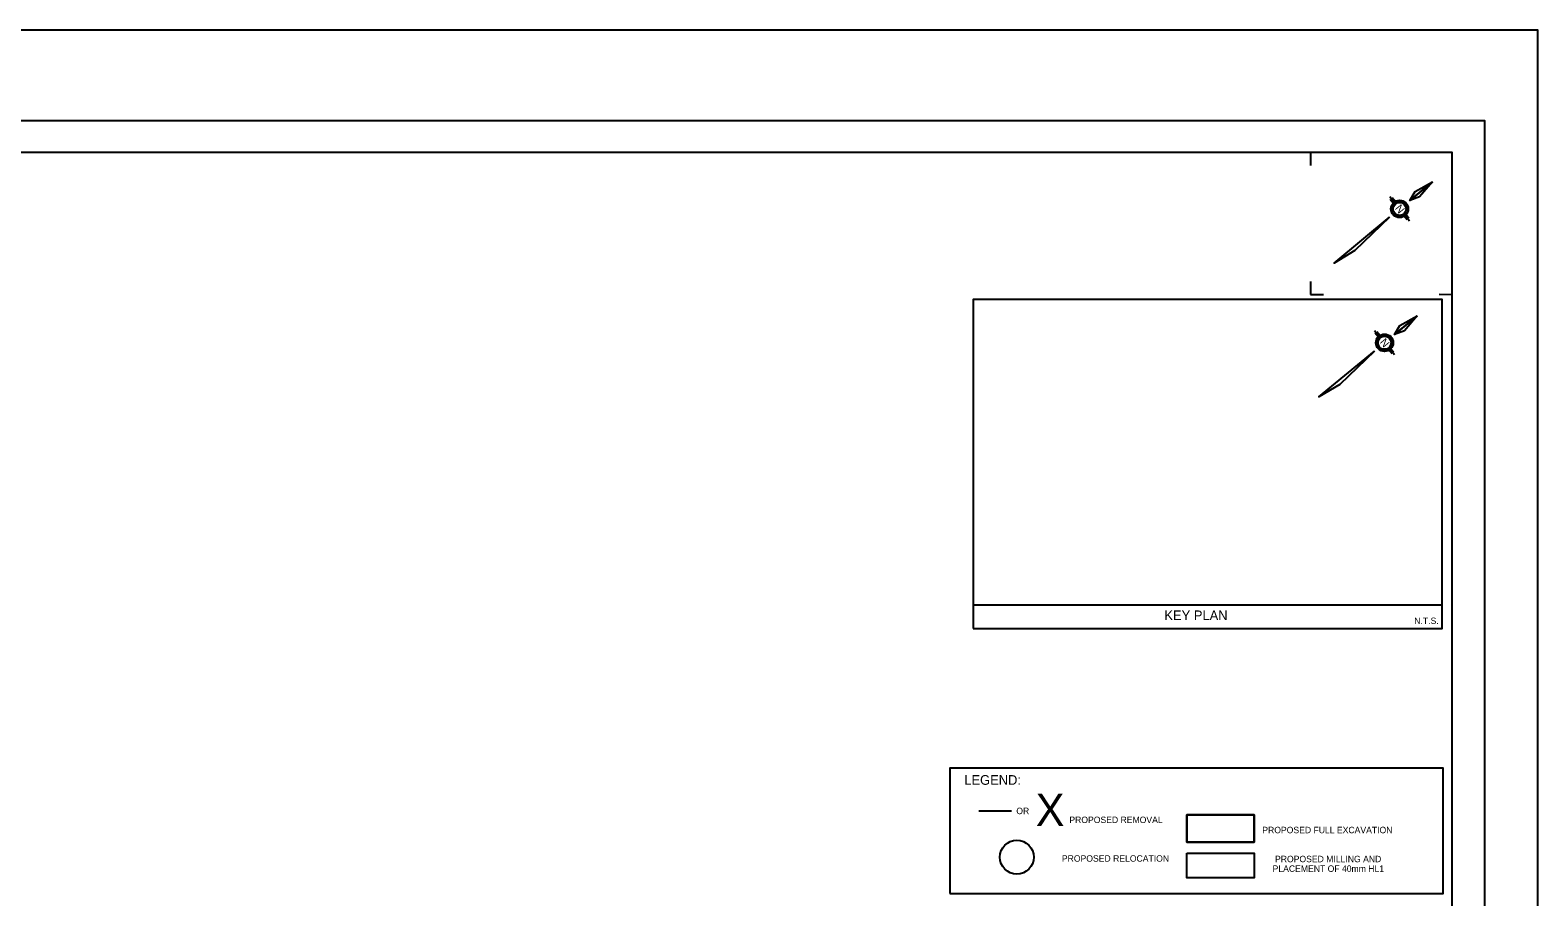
# Model space of a CAD drawing. Extents: x 595568 to 603431, y 4837996 to 4846579.
# Drawn here: x 603148.2 to 603265.3, y 4846476.1 to 4846543.4 of the extents above; entities that cross this region are included whole.
import ezdxf

# ---------------------------------------------------------------- set-up
doc = ezdxf.new("R2010")
doc.units = 0
for name, color, linetype in [('-PRINT FULLSIZE', 7, 'Continuous'), ('-PRINT HALFSIZE', 7, 'Continuous'), ('ENG_BORDER', 7, 'Continuous'), ('ENG_KEY', 7, 'Continuous'), ('ENG_LEGEND', 7, 'Continuous'), ('ENG_REMOVALS', 7, 'Continuous'), ('ENG_REMOVALS-LINEAR', 7, 'Continuous'), ('ENG_REMOVALS-RELOCATE', 7, 'Continuous'), ('ENG_SH_ASPHALT', 7, 'Continuous'), ('ENG_SH_CONCRETE', 7, 'Continuous'), ('ENG_TITLEBLOCK', 7, 'Continuous'), ('ENG_TX_LEGEND', 7, 'Continuous'), ('ENG_TX_REMOVALS', 7, 'Continuous')]:
    doc.layers.add(name, color=color, linetype=linetype)

msp = doc.modelspace()

# ---------------------------------------------------------------- linework, layer by layer
at = {"layer": '-PRINT FULLSIZE'}
msp.add_lwpolyline([(603041.76, 4846390.89), (603265.27, 4846390.89), (603265.27, 4846543.39), (603041.76, 4846543.39)], close=True, dxfattribs=at)
at = {"layer": '-PRINT HALFSIZE'}
msp.add_lwpolyline([(603056.66, 4846536.38), (603261.12, 4846536.38), (603261.12, 4846396.88), (603056.66, 4846396.88)], close=True, dxfattribs=at)
at = {"layer": 'ENG_BORDER'}
msp.add_lwpolyline([(603064.52, 4846399.38), (603258.62, 4846399.38), (603258.62, 4846533.88), (603064.52, 4846533.88)], close=True, dxfattribs=at)
at = {"layer": 'ENG_KEY'}
for p, q in [((603252.94, 4846519.64), (603252.59, 4846520.06)), ((603252.87, 4846519.58), (603252.64, 4846519.86)), ((603253.01, 4846519.69), (603252.78, 4846519.97)), ((603253.96, 4846518.27), (603253.73, 4846518.55)), ((603254.14, 4846518.18), (603253.8, 4846518.6)), ((603254.09, 4846518.38), (603253.86, 4846518.66)), ((603221.42, 4846498.78), (603257.84, 4846498.78))]:
    msp.add_line(p, q, dxfattribs=at)
for points in [[(603221.42, 4846496.95), (603257.84, 4846496.95), (603257.84, 4846522.47), (603221.42, 4846522.47)], [(603255.91, 4846521.22), (603254.91, 4846520.05), (603254.15, 4846519.77)], [(603255.91, 4846521.22), (603254.15, 4846519.77), (603254.57, 4846520.46)], [(603252.58, 4846518.47), (603249.89, 4846515.89), (603248.28, 4846514.92)]]:
    msp.add_lwpolyline(points, close=True, dxfattribs=at)
for radius in [0.675, 0.626, 0.504]:
    msp.add_circle((603253.37, 4846519.12), radius, dxfattribs=at)
at = {"layer": 'ENG_LEGEND'}
msp.add_lwpolyline([(603219.61, 4846476.36), (603257.91, 4846476.36), (603257.91, 4846486.09), (603219.61, 4846486.09)], close=True, dxfattribs=at)
at = {"layer": 'ENG_REMOVALS'}
msp.add_lwpolyline([(603238.01, 4846480.35), (603243.25, 4846480.35), (603243.25, 4846482.48), (603238.01, 4846482.48)], close=True, dxfattribs=at)
at = {"layer": 'ENG_REMOVALS-LINEAR'}
msp.add_line((603221.87, 4846482.78), (603224.41, 4846482.78), dxfattribs=at)
at = {"layer": 'ENG_REMOVALS-RELOCATE'}
msp.add_circle((603224.82, 4846479.19), 1.31, dxfattribs=at)
at = {"layer": 'ENG_SH_ASPHALT'}
msp.add_lwpolyline([(603238.01, 4846482.48), (603243.25, 4846482.48), (603243.25, 4846480.35), (603238.01, 4846480.35)], close=True, dxfattribs=at)
at = {"layer": 'ENG_SH_CONCRETE'}
msp.add_lwpolyline([(603238.01, 4846479.5), (603243.25, 4846479.5), (603243.25, 4846477.58), (603238.01, 4846477.58)], close=True, dxfattribs=at)
at = {"layer": 'ENG_TITLEBLOCK'}
for p, q in [((603247.62, 4846533.88), (603247.62, 4846532.88)), ((603254.11, 4846530.03), (603253.77, 4846530.45)), ((603254.05, 4846529.97), (603253.82, 4846530.25)), ((603254.19, 4846530.08), (603253.96, 4846530.36)), ((603255.13, 4846528.66), (603254.9, 4846528.94)), ((603255.32, 4846528.57), (603254.97, 4846528.99)), ((603255.27, 4846528.77), (603255.04, 4846529.05)), ((603247.62, 4846523.88), (603247.62, 4846522.88)), ((603247.62, 4846522.88), (603248.62, 4846522.88)), ((603257.62, 4846522.89), (603258.62, 4846522.88))]:
    msp.add_line(p, q, dxfattribs=at)
for points in [[(603257.09, 4846531.61), (603256.09, 4846530.44), (603255.33, 4846530.16)], [(603257.09, 4846531.61), (603255.33, 4846530.16), (603255.74, 4846530.85)], [(603253.76, 4846528.86), (603251.06, 4846526.28), (603249.45, 4846525.31)]]:
    msp.add_lwpolyline(points, close=True, dxfattribs=at)
for radius in [0.675, 0.626, 0.504]:
    msp.add_circle((603254.54, 4846529.51), radius, dxfattribs=at)

# ---------------------------------------------------------------- texts
at = {"layer": 'ENG_KEY'}
msp.add_text('N', height=0.599, rotation=309.5559, dxfattribs=at).set_placement((603252.97, 4846519.15))
at = {"layer": 'ENG_REMOVALS'}
msp.add_text('X', height=2.5, rotation=360, dxfattribs=at).set_placement((603226.29, 4846481.61))
at = {"layer": 'ENG_TITLEBLOCK'}
msp.add_text('N', height=0.599, rotation=309.5559, dxfattribs=at).set_placement((603254.15, 4846529.54))
at = {"layer": 'ENG_TX_LEGEND'}
for s, height, p in [('KEY PLAN', 0.75, (603236.28, 4846497.59)), ('N.T.S.', 0.5, (603255.68, 4846497.29)), ('LEGEND:', 0.75, (603220.74, 4846484.81))]:
    msp.add_text(s, height=height, rotation=360, dxfattribs=at).set_placement(p)
at = {"layer": 'ENG_TX_REMOVALS'}
for s, p in [('OR', (603224.78, 4846482.53)), ('PROPOSED REMOVAL', (603228.9, 4846481.84)), ('PROPOSED FULL EXCAVATION', (603243.88, 4846481.05)), ('PROPOSED RELOCATION', (603228.32, 4846478.84)), ('PLACEMENT OF 40mm HL1', (603244.68, 4846478.05)), ('PROPOSED MILLING AND', (603244.87, 4846478.8))]:
    msp.add_text(s, height=0.5, rotation=360, dxfattribs=at).set_placement(p)

doc.saveas('drawing.dxf')
